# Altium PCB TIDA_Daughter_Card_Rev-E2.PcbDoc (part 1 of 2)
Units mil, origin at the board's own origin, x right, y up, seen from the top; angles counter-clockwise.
Board outline 3149.06 x 866.14 mil, 6 copper layers (L1-Top Layer, L2-GND1, L3-SIG1, L4-PWR, L5-GND2, L6-Bottom Layer), stack 0 mil thick; 80 components, 50 nets, 307 pads, 118 vias.
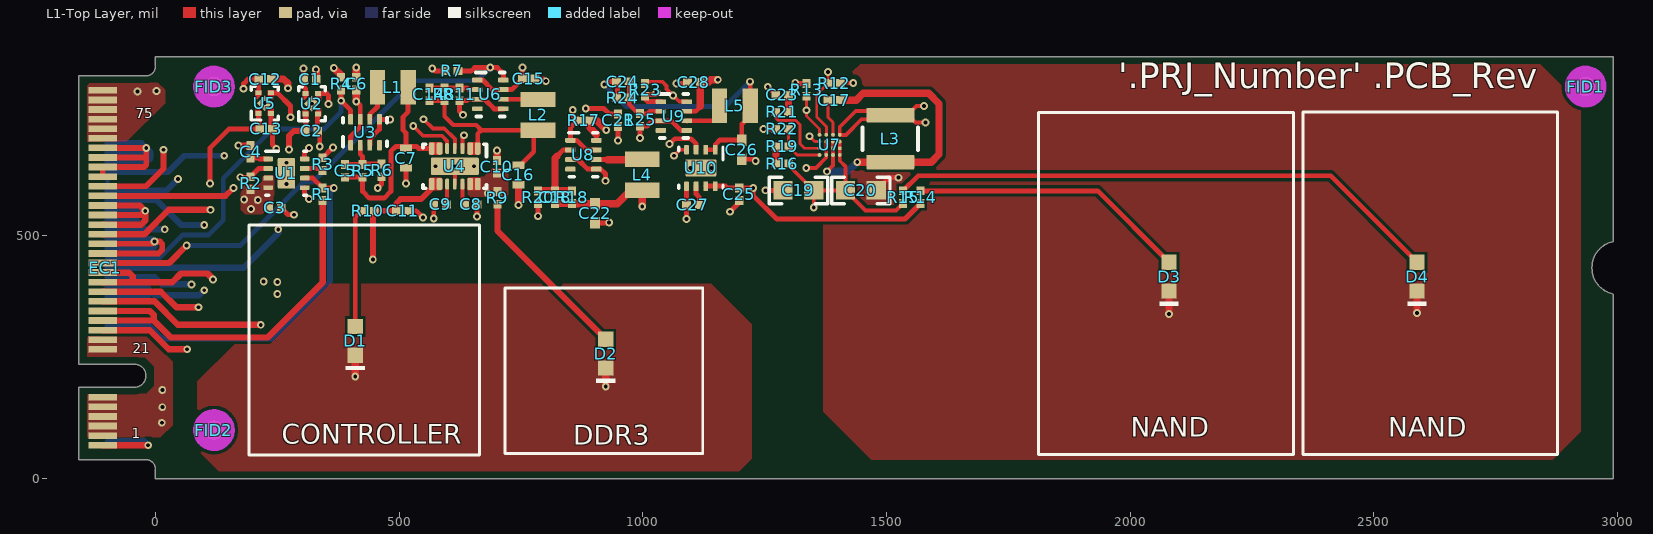
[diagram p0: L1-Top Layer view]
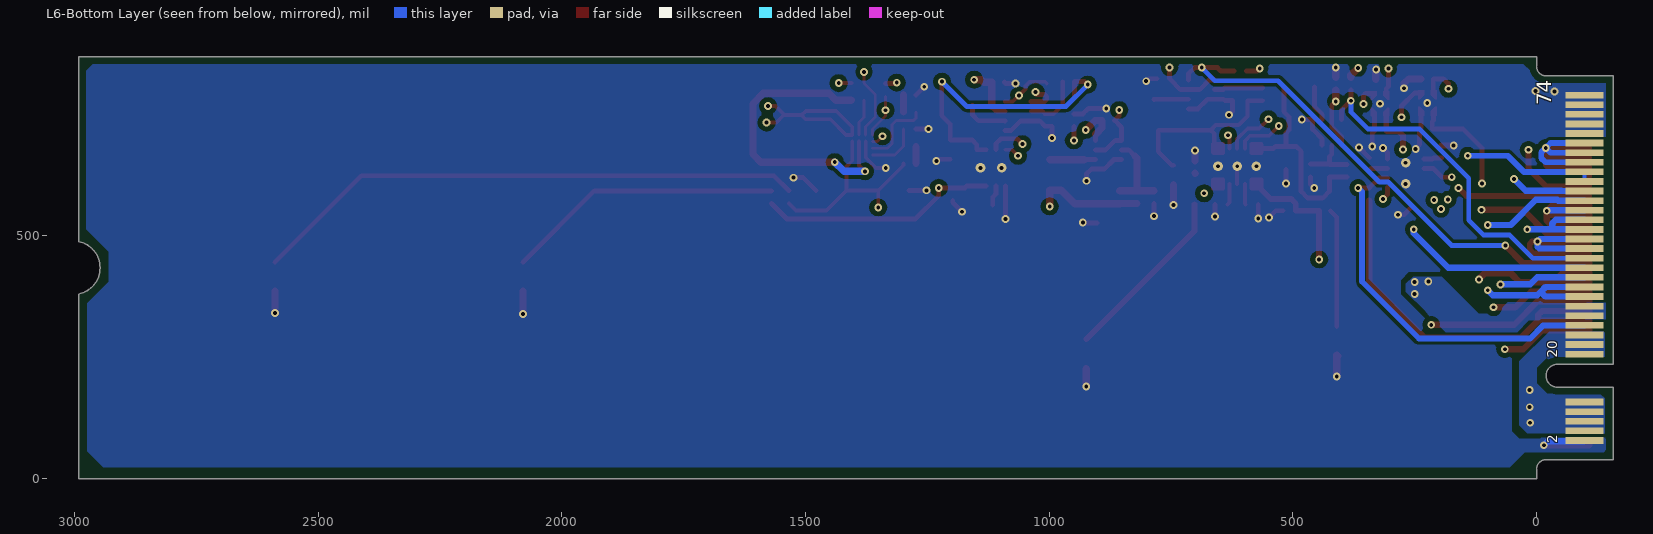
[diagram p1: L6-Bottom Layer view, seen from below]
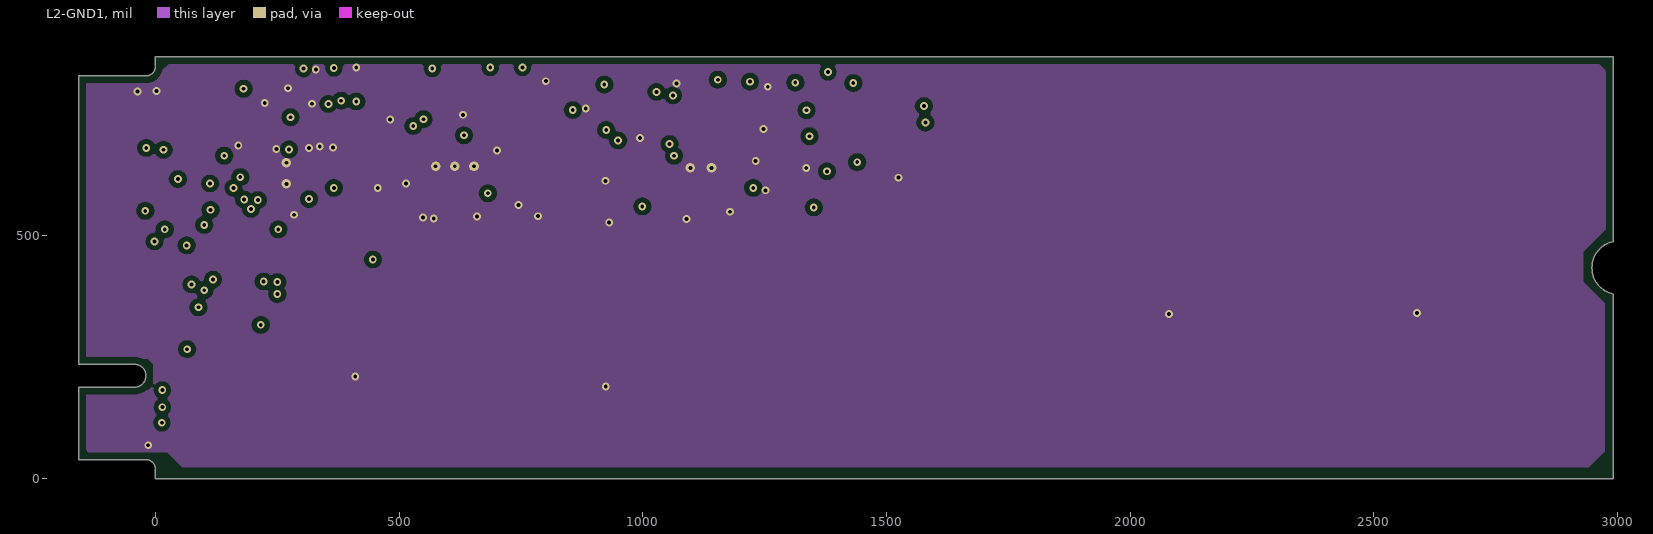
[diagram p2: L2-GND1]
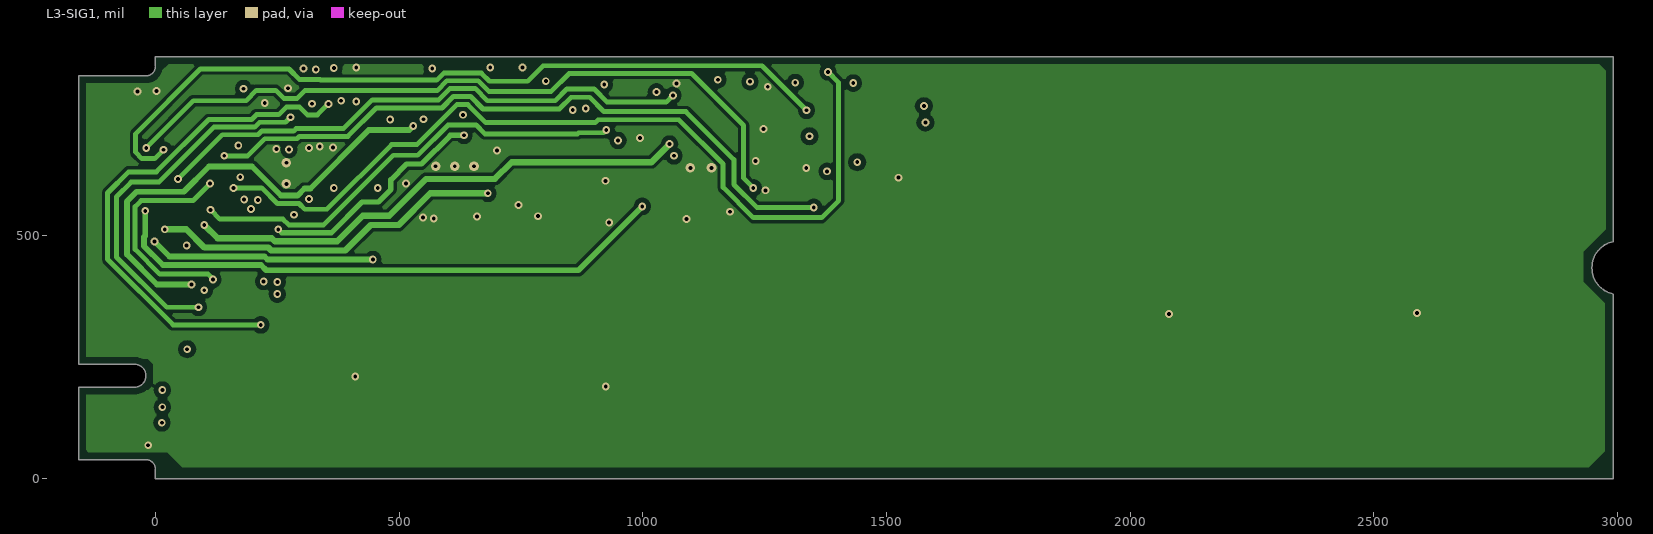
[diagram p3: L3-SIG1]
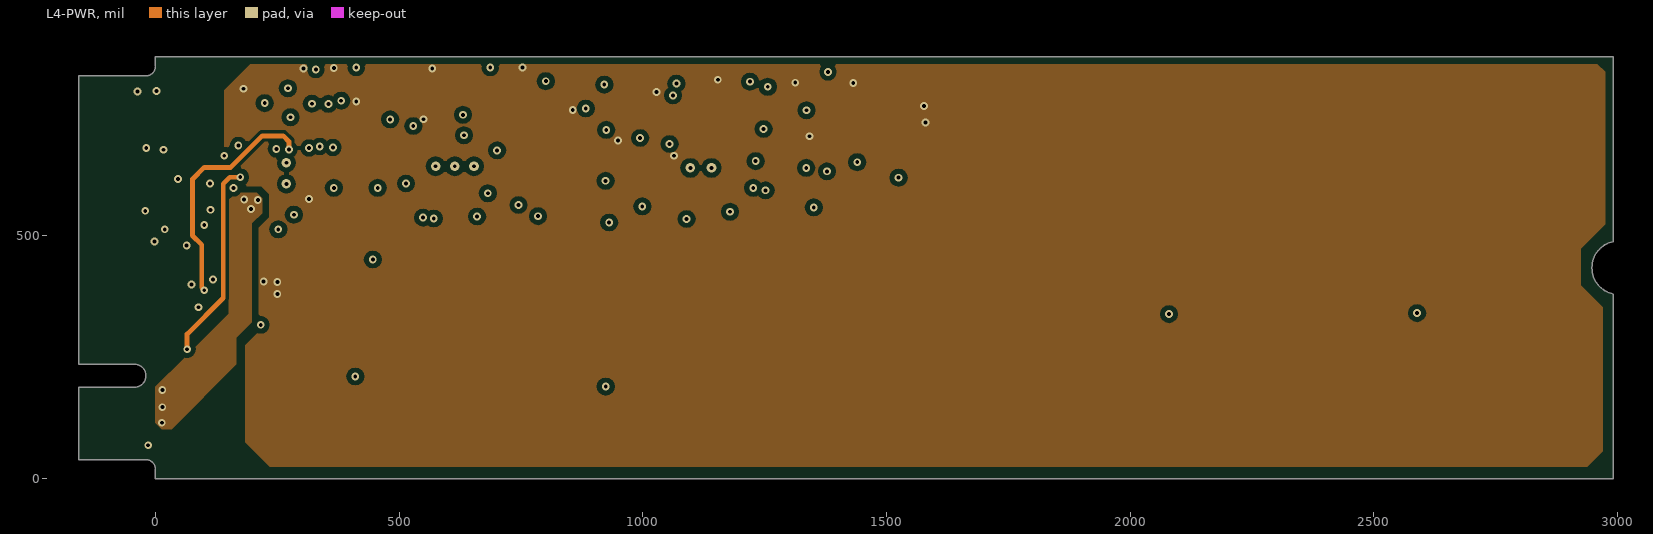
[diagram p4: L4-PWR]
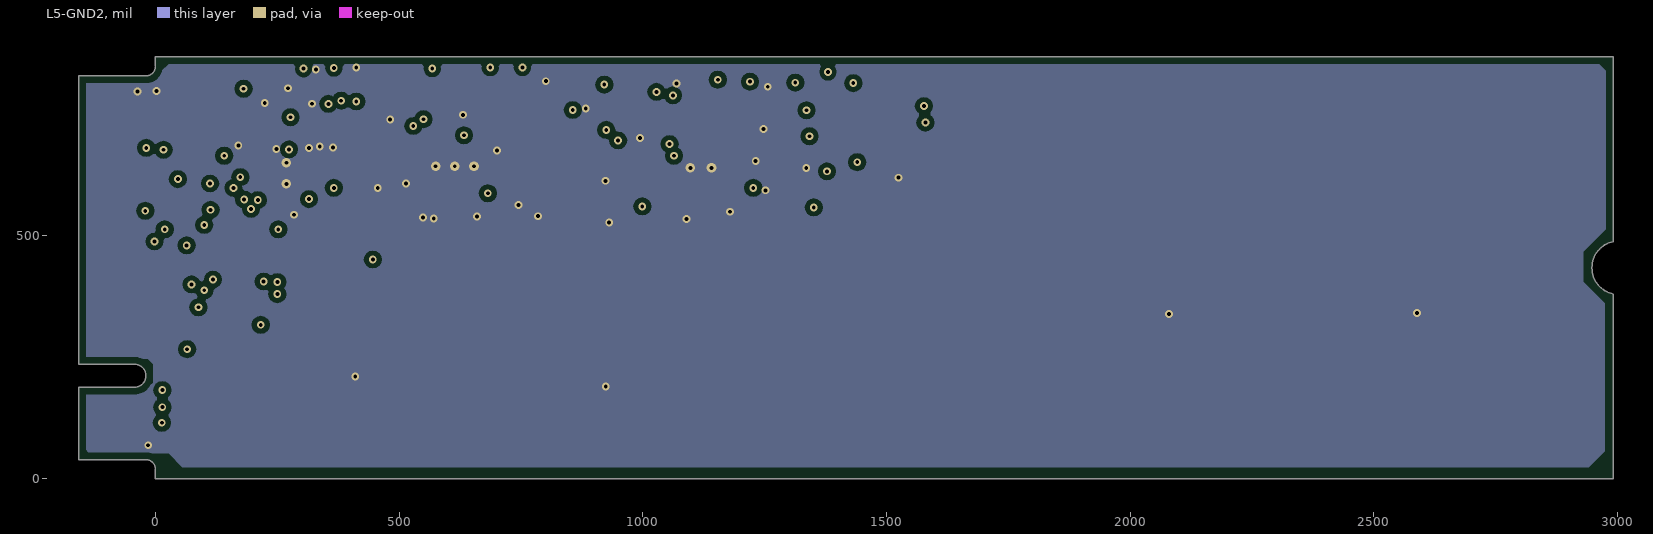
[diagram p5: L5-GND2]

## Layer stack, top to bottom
L1-Top Layer: signal copper (thickness not stored)
L2-GND1: signal copper (thickness not stored)
L3-SIG1: signal copper (thickness not stored)
L4-PWR: signal copper (thickness not stored)
L5-GND2: signal copper (thickness not stored)
L6-Bottom Layer: signal copper (thickness not stored)

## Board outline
-157.48,187.99 -43.31,187.99 ccw(c-43.31,211.61) -43.31,235.24 -157.48,235.24 -157.48,826.77 -19.69,826.77 ccw(c-19.69,846.46) 0,846.46 0,866.14 2991.58,866.14 2991.58,486.9 2991.54,486.9 ccw(c3002.82,433.07) 2991.54,379.24 2991.58,379.24 2991.58,0.39 2991.18,0 0,0 0,19.69 ccw(c-19.69,19.69) -19.69,39.37 -157.48,39.37

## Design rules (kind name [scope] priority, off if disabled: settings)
AcuteAngle [All] p1: minimum=4.50000000000000E+0001 checktracksonly=FALSE
AssemblyTestPointUsage [All] p1: valid=2
BoardOutlineClearance BoardOutlineClearance_MountingHoles [OnCopper and InComponentClass('Mounting Holes')] p1: gap=40 ignorepadtopadclearanceinfootprint=FALSE
BoardOutlineClearance BoardOutlineClearance_Poly [OnCopper and IsPoly] p2: gap=15 ignorepadtopadclearanceinfootprint=FALSE
BoardOutlineClearance [OnCopper and Not InComponentClass('Logo') and not InComponentClass('FiducialMark') and not InRegion(1000,500,4000,800) and not InPoly] p3: gap=12 ignorepadtopadclearanceinfootprint=FALSE
Clearance "U2 and U5 Pad Class" [(InPadClass('U2 AND U5'))] p1: gap=8 ignorepadtopadclearanceinfootprint=TRUE except(0: Arc-Hole Track-Hole SMDPad-Hole THPad-Hole Via-Hole Fill-Hole Poly-Hole Region-Hole Text-Hole; 4.6: Track-SMDPad SMDPad-Region; 6: Arc-Arc Arc-Track Arc-SMDPad Track-Track; 6.8: Via-Poly Via-Region; 7.4: SMDPad-Via)
Clearance Clearance_Keepouts [((IsTrack Or IsArc) And Not InPoly) And IsFree and IsKeepOut vs ((IsTrack Or IsArc) And Not InPoly) And IsFree and IsKeepOut] p2: gap=0 ignorepadtopadclearanceinfootprint=TRUE
Clearance Clearance_Poly [InPolygon] p3: gap=10 ignorepadtopadclearanceinfootprint=TRUE except(6: SMDPad-Fill SMDPad-Poly SMDPad-Region Fill-Fill Fill-Poly Fill-Region Poly-Poly Poly-Region Region-Region; 7: Arc-Fill Arc-Poly Arc-Region Track-Fill Track-Poly Track-Region)
Clearance Clearance_FiducialMark [IsKeepOut and InComponentClass('FiducialMark') vs IsPad and InComponentClass('FiducialMark')] p4: gap=0 ignorepadtopadclearanceinfootprint=FALSE
Clearance [All] p5: gap=7.87 ignorepadtopadclearanceinfootprint=TRUE except(0: Arc-Hole Track-Hole SMDPad-Hole THPad-Hole Via-Hole Fill-Hole Poly-Hole Region-Hole Text-Hole; 5.6: Arc-SMDPad Track-SMDPad; 5.7: Arc-Arc Arc-Track Track-Track; 5.8: Track-Region; 5.9: SMDPad-Poly SMDPad-Region; 6.1: Via-Region; 10: Fill-Poly Poly-Poly)
ComponentClearance ComponentClearance_MountingHoles_FiducialMarks [InComponentClass('Mounting Holes') vs InComponentClass('FiducialMark')] p1: gap=50 collisioncheckmode=3 verticalgap=10 showdistances=FALSE
ComponentClearance ComponentClearance_Shunt [InComponentClass('Header') vs InComponentClass('Shunt')] p2: gap=0 collisioncheckmode=3 verticalgap=0 showdistances=FALSE
ComponentClearance ComponentClearance_Logo [InComponentClass('Logo')] p3: gap=50 collisioncheckmode=3 verticalgap=10 showdistances=FALSE
ComponentClearance ComponentClearance_ScrewToNut [(HasFootprint('NY PMS 440 0025 PH')) vs (HasFootprint('Keystone_1902C'))] p4: gap=5 collisioncheckmode=3 verticalgap=10 showdistances=FALSE
ComponentClearance ComponentClearance_MountingHoles [InComponentClass('Mounting Holes')] p5: gap=250 collisioncheckmode=3 verticalgap=100000 showdistances=FALSE
ComponentClearance ComponentClearance_SmallPassives [HasFootprint('0201*') or HasFootprint('0402*') or HasFootprint('0508') or HasFootprint('0603*') or HasFootprint('0612') or HasFootprint('0805*') or HasFootprint('0815*') or HasFootprint('0830*') or HasFootprint('1206*') or HasFootprint('1210*') or HasFootprint('1808*') or HasFootprint('1812*') or HasFootprint('1825*') or HasFootprint('2010*') or HasFootprint('2220*') or HasFootprint('2225*') or HasFootprint('2512*') or HasFootprint('2728*') or HasFootprint('3518*') vs HasFootprint('0201*') or HasFootprint('0402*') or HasFootprint('0508') or HasFootprint('0603*') or HasFootprint('0612') or HasFootprint('0805*') or HasFootprint('0815*') or HasFootprint('0830*') or HasFootprint('1206*') or HasFootprint('1210*') or HasFootprint('1808*') or HasFootprint('1812*') or HasFootprint('1825*') or HasFootprint('2010*') or HasFootprint('2220*') or HasFootprint('2225*') or HasFootprint('2512*') or HasFootprint('2728*') or HasFootprint('3518*')] p6: gap=14.96 collisioncheckmode=3 verticalgap=10 showdistances=FALSE
ComponentClearance ComponentClearance_THtoSMT [IsThruComponent vs IsSMTComponent] p7: gap=40 collisioncheckmode=3 verticalgap=30 showdistances=FALSE
ComponentClearance ComponentClearance_THtoTH [IsThruComponent vs IsThruComponent] p8: gap=30 collisioncheckmode=3 verticalgap=30 showdistances=FALSE
ComponentClearance [All] p9: gap=15 collisioncheckmode=3 verticalgap=10 showdistances=FALSE
DiffPairsRouting [All] p1: maxlimit=100 minlimit=10 mostfreqgap=10 toplayer_minwidth=15 toplayer_maxwidth=15 toplayer_prefwidth=15 midlayer1_minwidth=15 midlayer1_maxwidth=15 midlayer1_prefwidth=15 midlayer2_minwidth=15 midlayer2_maxwidth=15 midlayer2_prefwidth=15 midlayer3_minwidth=15 midlayer3_maxwidth=15 midlayer3_prefwidth=15 midlayer4_minwidth=15 midlayer4_maxwidth=15 midlayer4_prefwidth=15 bottomlayer_minwidth=15 bottomlayer_maxwidth=15 bottomlayer_prefwidth=15 maxuncoupledlength=1000
FabricationTestPointUsage TestPointUsage [All] p1: valid=2 allowmultiple=FALSE
FabricationTestpoint Testpoint [All] p1: side=3 testpointundercomponent=TRUE minsize=40 maxsize=100 preferedsize=60 minholesize=0 maxholesize=40 preferedholesize=32 testpointgrid=1 allowsidetop=TRUE allowsidebottom=TRUE usegrid=TRUE gridtolerance=0.01
FanoutControl Fanout_LCC [IsLCC] p1: bgadir=Out bgaviamode=Centered fanoutstyle=Auto fanoutdirection=Alternating viagrid=1 // Fanout_LCC (Default Rule)
FanoutControl Fanout_BGA [IsBGA] p2: bgadir=Out bgaviamode=Centered fanoutstyle=Auto fanoutdirection=Alternating viagrid=1 // Fanout_BGA (Default Rule)
FanoutControl Fanout_Default [All] p4: bgadir=Out bgaviamode=Centered fanoutstyle=Auto fanoutdirection=Alternating viagrid=1 // Fanout_Default (Default Rule)
FanoutControl Fanout_Small [(CompPinCount < 5)] p5: bgadir=Out bgaviamode=Centered fanoutstyle=Auto fanoutdirection=OutThenIn viagrid=1 // Fanout_Small (Default Rule)
HoleSize [All] p1: absolutevalues=TRUE maxlimit=251 minlimit=7.87 maxpercent=80.000 minpercent=20.000
MinimumAnnularRing MinimumAnnularRing_ThermalPadVias [IsVia and InAnyComponent] p1: minimumring=5.91
MinimumAnnularRing [All] p2: minimumring=4
MinimumSolderMaskSliver MinimumSolderMaskSliver_Logo [InComponentClass('Logo') vs InComponentClass('Logo')] p1: minsoldermaskwidth=0.7
MinimumSolderMaskSliver [All] p2: minsoldermaskwidth=3.2
PlaneConnect [All] p1: planeconnectstyle=Direct reliefexpansion=10 reliefentries=4 reliefconductorwidth=10 reliefairgap=10
PolygonConnect [All] p1: connectstyle=Direct reliefconductorwidth=10 reliefentries=4 polygonreliefangle="90 Angle" airgapwidth=10
RoutingVias ThermalPadVias [IsVia and InAnyComponent] p1: holewidth=7.87 width=19.68 viastyle="Through Hole" minholewidth=7.87 minwidth=19.68 maxholewidth=12.99 maxwidth=23.62
RoutingVias [All] p2: holewidth=8 width=24 viastyle="Through Hole" minholewidth=7.87 minwidth=16 maxholewidth=40 maxwidth=65
SilkToBoardRegionClearance [Not ((IsComment or IsDesignator) And (Hide <> 'False')) and not InRegion(1000,500,4000,800)] p1:
SilkToSilkClearance SilkToSilkClearance_Pb-FreeLogo [(HasFootprint('Pb-Free_Overlay_Medium') OR HasFootprint('Pb-Free_Overlay_Small')) vs (HasFootprint('Pb-Free_Overlay_Medium') OR HasFootprint('Pb-Free_Overlay_Small'))] p1: silktosilkclearance=0
SilkToSilkClearance [All] p2: silktosilkclearance=2
SilkToSolderMaskClearance SilkToComponentPadClearance [(IsPad or IsFill or IsRegion) and InAnycomponent] p1: minsilkscreentomaskgap=3 clearancetoexposedcopper=TRUE
SilkToSolderMaskClearance "Silk to Solder Mask Opening" [All] p2: minsilkscreentomaskgap=3 clearancetoexposedcopper=FALSE
SolderMaskExpansion [All] p1: expansion=1.97
Width [All] p1: maxlimit=100 minlimit=6 preferedwidth=10 checkconnectedcopper=TRUE
15 further rules are at their usual default settings.

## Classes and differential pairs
component class Sheet1: U?
component class Daughter_Card_Sheet2: C1 C2 C5 C6 C7 C8 C9 C10 C11 C12 C13 C14 C15 C16 C17 C18 C19 C20 C21 C22 C23 C24 C25 C26 C27 C28 D1 D2 D3 D4 L1 L2 L3 L4 L5 R4 R5 R6 R7 R8 R9 R10 R11 R12 R13 R14 R15 R16 R17 R18 R19 R20 R21 R22 R23 R24 R25 U2 U3 U4 U5 U6 U7 U8 U9 U10
component class Daughter_Card_Sheet1: C3 C4 EC1 R1 R2 R3 U1
component class EVM_Hardware: FID1 FID2 FID3 ZZ1 ZZ2 ZZ3 ZZ4
component class FiducialMark: FID1 FID2 FID3
component class AssemblyNote: ZZ1 ZZ2 ZZ3 ZZ4
pad class "U2 AND U5": U2-1 U2-2 U2-3 U2-4 U2-5 U5-1 U5-2 U5-3 U5-4 U5-5

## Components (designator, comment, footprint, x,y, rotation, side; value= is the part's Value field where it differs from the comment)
C1 "GRM033R60J104KE19D" 0201_033 317,820 r0 top value=0.1uF
C2 "GRM033R60J104KE19D" 0201_033 319.84,713.82 r0 top value=0.1uF
C3 "GRM033R60J104KE19D" 0201_033 245,556 r0 top value=0.1uF
C4 "GRM033R60J103KA01D" 0201 195,670.99 r90 top value=0.01uF
C5 "GRM033R71C101KA01D" 0201 389,632 r90 top value=100pF
C6 "GRM035R60J475ME15D" 0201 412,811.01 r90 top value=4.7uF
C7 "GRM155R60J226ME11D" 0402S 514,658.38 r270 top value=22uF
C8 "GRM033R71C102KA01D" 0201 647,563 r0 top value=1000pF
C9 "GRM033R71C102KA01D" 0201 584.01,563 r180 top value=1000pF
C10 "CL03A105MP3NSNC" 0201 700.79,640 r90 top value=1uF
C11 "CL03A105MP3NSNC" 0201 507,550 r0 top value=1uF
C12 "GRM033R60J104KE19D" 0201_033 224.8,820.48 r0 top value=0.1uF
C13 "GRM033R60J104KE19D" 0201_033 227,718 r0 top value=0.1uF
C14 "GRM033R71C101KA01D" 0201 562,789 r90 top value=100pF
C15 "GRM035R60J475ME15D" 0201 766.01,821 r0 top value=4.7uF
C16 "GRM155R60J226ME11D" 0402S 744.79,623.62 r270 top value=22uF
C17 "GRM033R60J104KE19D" 0201_033 1393.01,777 r0 top value=0.1uF
C18 "GRM033R71C101KA01D" 0201 820,578 r90 top value=100pF
C19 "GRM188R61E106MA73D" 0603 1319.44,592 r180 top value=10uF
C20 "GRM188R61E106MA73D" 0603 1447.44,592 r0 top value=10uF
C21 "GRM035R60J475ME15D" 0201 949.36,736 r90 top value=4.7uF
C22 "GRM155R60J226ME11D" 0402L 902,545 r270 top value=22uF
C23 "GRM033R71E681KA01D" 0201 1286.01,788 r0 top value=680pF
C24 "GRM033R71C101KA01D" 0201 959,815 r0 top value=100pF
C25 "GRM033R60J104KE19D" 0201_033 1198,584 r270 top value=0.1uF
C26 "GRM155R60J226ME11D" 0402L 1203,675.62 r270 top value=22uF
C27 "GRM033R71C102KA01D" 0201 1103,562 r180 top value=1000pF
C28 "GRM035R60J475ME15D" 0201 1105,814 r180 top value=4.7uF
D1 "LB Q39G-L2N2-35-1" "LB Q39G_BLUE" 410,283 r270 top value=Blue
D2 "LB Q39G-L2N2-35-1" "LB Q39G_BLUE" 924,257 r270 top value=Blue
D3 "LB Q39G-L2N2-35-1" "LB Q39G_BLUE" 2080,415 r270 top value=Blue
D4 "LB Q39G-L2N2-35-1" "LB Q39G_BLUE" 2589,415 r270 top value=Blue
EC1 "EDGE_CONN_SM3ZS067U310ABR1200" JAE_EDGE_CONN_SM3ZS067U310ABR1200 -108.27,433.07 r90 top locked
FID1 "Fiducial" Fiducial10-20 2935,805 r0 top
FID2 "Fiducial" Fiducial10-20 120,100 r0 top
FID3 "Fiducial" Fiducial10-20 120,805 r0 top
L1 "DFE201610E-R47M=P2" DFE201610E 487,804 r180 top value=470nH
L2 "DFE201610E-R47M=P2" DFE201610E 785,747 r90 top value=470nH
L3 "DFE322512F-2R2M=P2" DFE322512 1508,698 r270 top value=2.2uH
L4 "DFE201610E-R47M=P2" DFE201610E 999,624 r90 top value=470nH
L5 "DFE201610E-R47M=P2" DFE201610E 1189,766 r180 top value=470nH
R1 "RC0201JR-07100KL" 0201 343,584 r270 top value=100k
R2 "RC0201JR-07100KL" 0201 195,606.99 r270 top value=100k
R3 "RC0201FR-07536RL" 0201 343,646 r270 top value=536
R4 "RC0201JR-07100KL" 0201 381,811 r90 top value=100k
R5 "RC0201FR-0790K9L" 0201 425,632 r270 top value=90.9k
R6 "RC0201JR-07100KL" 0201 464,633 r90 top value=100k
R7 "RC0201JR-07100KL" 0201 608,837 r180 top value=100k
R8 "RC0201FR-07150KL" 0201 593,789.01 r270 top value=150k
R9 "RC0201JR-07100RL" 0201 701.6,576.33 r90 top value=100
R10 "RC0201JR-07100RL" 0201 436,550 r0 top value=100
R11 "RC0201JR-07100KL" 0201 624,789.01 r90 top value=100k
R12 "RC0201JR-07100KL" 0201 1393.01,812 r0 top value=100k
R13 "RC0201JR-07100KL" 0201 1336,798 r270 top value=100k
R14 "RC0201JR-07100RL" 0201 1570,578.01 r270 top value=100
R15 "RC0201JR-07100RL" 0201 1534.12,578.06 r270 top value=100
R16 "RC0201JR-07910KL" 0201 1286.44,647 r0 top value=910k
R17 "RC0201JR-07100KL" 0201 878.75,735.53 r180 top value=100k
R18 "RC0201JR-07100KL" 0201 855,578 r270 top value=100k
R19 "RC0201FR-071ML" 0201 1286.44,682 r180 top value=1.00Meg
R20 "RC0201JR-07100KL" 0201 785,578 r90 top value=100k
R21 "RC0201FR-0761K9L" 0201 1286.01,753 r180 top value=61.9k
R22 "RC0201JR-07100KL" 0201 1286.01,718 r0 top value=100k
R23 "RC0201JR-07100KL" 0201 1005,798 r270 top value=100k
R24 "RC0201FR-07365KL" 0201 959,782 r180 top value=365k
R25 "RC0201JR-07100KL" 0201 994.57,736.58 r90 top value=100k
U1 "TPS259521DSGR" DSG0008A 268.6,626.99 r0 top
U2 "TLV74333PDQNR" DQN0004A 321.03,769.81 r90 top
U3 "TPS62821DLCR" DLC0008A 430,711 r90 top
U4 "TPS22976DPUR" DPU0014A 614.25,641.42 r270 top
U5 "TLV74318PDQNR" DQN0004A 224.1,771.07 r90 top
U6 "TPS62821DLCR" DLC0008A 687.21,788.84 r0 top
U7 "TPS61372YKBT" YKB0016AEAG 1383.5,685.24 r90 top
U8 "TPS62821DLCR" DLC0008A 878.17,665.06 r0 top
U9 "TPS62822DLCR" DLC0008A 1063.8,744.47 r0 top
U10 "TPS22975DSGR" DSG0008A 1119.28,638 r270 top
ZZ1 "This Assembly Note is for PCB labels only" AssemblyNoteLabel 26.57,2103.91 r0 top
ZZ2 "These assemblies are ESD sensitive, ESD precautions shall be observed." AssemblyNote 26.57,1995.02 r0 top
ZZ3 "These assemblies must be clean and free from flux and all contaminants. Use of no clean flux is not acceptable." AssemblyNote 26.57,1906.46 r0 top
ZZ4 "These assemblies must comply with workmanship standards IPC-A-610 Class 2, unless otherwise specified." AssemblyNote 26.57,1817.91 r0 top

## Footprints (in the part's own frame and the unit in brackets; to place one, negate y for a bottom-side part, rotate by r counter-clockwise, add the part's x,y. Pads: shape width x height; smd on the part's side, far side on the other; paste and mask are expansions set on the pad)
0201 [mm] "Data from Kemet datasheet CC101_COM dated 7/28/11"
  rect 0.46x0.42 smd mask+0.048: 1(-0.33,0) 2(0.33,0)
  body extent -0.31,-0.16 0.31,0.16, height 0.26
0201_033 [mm] "SMD, 2-Leads, Height 0.33mm"
  rect 0.46x0.42 smd mask+0.048: 1(-0.33,0) 2(0.33,0)
  body extent -0.31,-0.16 0.31,0.16, height 0.33
0402L [mm] "0402 from SM-752 data"
  rect 0.6x0.5 smd: 1(-0.5,0) 2(0.5,0)
  body extent -0.55,-0.3 0.55,0.3, height 0.6
0402S [mil] "Based on C0402S footprint from PADS legacy"
  rect 15x24 smd: 1(-20,0) 2(20,0)
  body extent -22,-12 22,12, height 24
0603 [mm] "0603 from SM-752 data"
  rect 1x0.95 smd: 1(-0.8,0) 2(0.8,0)
  silkscreen extent -1.52,-0.69 1.52,0.69, body extent -0.87,-0.47 0.87,0.47, height 1
AssemblyNote [mil] "Assembly Note"
AssemblyNoteLabel [mil] "Assembly Note for PCB Labels"
DFE201610E [mm] "MuRata"
  rect 0.8x1.8 smd: 1(0.8,0) 2(-0.8,0)
  body extent -1.1,-0.9 1.1,0.9, height 1
DFE322512 [mm] "MuRata"
  rrect13% 0.75x2.5 smd: 1(-1.225,0) 2(1.225,0)
  silkscreen extent -0.6,-1.45 0.6,1.45, body extent -1.7,-1.35 1.7,1.35, height 1.2
DLC0008A [mm] "VSON-HR-8"
  rrect40% 0.55x0.25 smd: 1(-0.675,0.75) 2(-0.675,0.25) 3(-0.675,-0.25) 4(-0.675,-0.75) 5(0.675,-0.75) 6(0.675,-0.25) 7(0.675,0.25) 8(0.675,0.75)
  silkscreen extent -0.75,-1.15 0.75,1.15, body extent -0.8,-1.05 0.8,1.05, height 1.02
DPU0014A [mm] "SON-14"
  rrect67% 0.65x0.3 smd paste-0.05 mask-0.05: 1(-0.925,1.2) 2(-0.925,0.8) 6(-0.925,-0.8) 7(-0.925,-1.2) 8(0.925,-1.2) 9(0.925,-0.8) 13(0.925,0.8) 14(0.925,1.2)
  rrect50% 0.55x0.2 smd: 3(-0.925,0.4) 4(-0.925,0) 5(-0.925,-0.4) 10(0.925,-0.4) 11(0.925,0) 12(0.925,0.4)
  rrect12% 0.85x1.11 on Top Paste: 15(0,0.655) 15(0,-0.655)
  rrect11% 0.9x2.5 smd paste-0.5: 15(0,0)
  L1-Top Layer region: -0.6,0.75 -0.6,1.25 -0.613,1.3 -0.65,1.337 -0.7,1.35 -0.7,1.35 -1.15,1.35 -1.188,1.342 -1.221,1.321 -1.242,1.288 -1.25,1.25 -1.25,1.25 -1.25,0.75 -1.242,0.712 -1.221,0.679 -1.188,0.658 -1.15,0.65 -1.15,0.65 -0.7,0.65 -0.662,0.658 -0.629,0.679 -0.608,0.712 -0.6,0.75
  L1-Top Layer region: -0.6,-0.75 -0.6,-1.25 -0.613,-1.3 -0.65,-1.337 -0.7,-1.35 -0.7,-1.35 -1.15,-1.35 -1.188,-1.342 -1.221,-1.321 -1.242,-1.288 -1.25,-1.25 -1.25,-1.25 -1.25,-0.75 -1.242,-0.712 -1.221,-0.679 -1.188,-0.658 -1.15,-0.65 -1.15,-0.65 -0.7,-0.65 -0.662,-0.658 -0.629,-0.679 -0.608,-0.712 -0.6,-0.75
  L1-Top Layer region: 0.6,-0.75 0.6,-1.25 0.613,-1.3 0.65,-1.337 0.7,-1.35 0.7,-1.35 1.15,-1.35 1.188,-1.342 1.221,-1.321 1.242,-1.288 1.25,-1.25 1.25,-1.25 1.25,-0.75 1.242,-0.712 1.221,-0.679 1.188,-0.658 1.15,-0.65 1.15,-0.65 0.7,-0.65 0.662,-0.658 0.629,-0.679 0.608,-0.712 0.6,-0.75
  L1-Top Layer region: 0.6,0.75 0.6,1.25 0.613,1.3 0.65,1.337 0.7,1.35 0.7,1.35 1.15,1.35 1.188,1.342 1.221,1.321 1.242,1.288 1.25,1.25 1.25,1.25 1.25,0.75 1.242,0.712 1.221,0.679 1.188,0.658 1.15,0.65 1.15,0.65 0.7,0.65 0.662,0.658 0.629,0.679 0.608,0.712 0.6,0.75
  silkscreen extent -1.15,-1.65 1.15,1.65, body extent -1.05,-1.55 1.05,1.55, height 0.8
DQN0004A [mm] "SON, 0.65mm pitch"
  rect 0.25x0.31 smd paste-1 mask-0.31: 1(-0.535,0.325) 2(-0.535,-0.325) 3(0.535,-0.325) 4(0.535,0.325)
  rect 0.58x0.58 smd rot 45 paste-0.065: 5(0,0)
  L1-Top Layer region: -0.66,0.48 -0.2,0.48 -0.2,0.379 -0.409,0.17 -0.66,0.17
  L1-Top Layer region: 0.66,0.48 0.2,0.48 0.2,0.379 0.409,0.17 0.66,0.17
  L1-Top Layer region: 0.66,-0.48 0.2,-0.48 0.2,-0.379 0.409,-0.17 0.66,-0.17
  L1-Top Layer region: -0.66,-0.48 -0.2,-0.48 -0.2,-0.379 -0.409,-0.17 -0.66,-0.17
  silkscreen extent -0.88,-0.7 0.88,0.7, body extent -0.53,-0.53 0.53,0.53, height 0.42
DSG0008A [mm] "SON, 8-Leads, Body 2x2mm, Pitch 0.5mm, Thermal Pad 1.6x0.9mm, TI Recommended"
  rrect40% 0.5x0.25 smd: 1(-0.95,0.75) 2(-0.95,0.25) 3(-0.95,-0.25) 4(-0.95,-0.75) 5(0.95,-0.75) 6(0.95,-0.25) 7(0.95,0.25) 8(0.95,0.75)
  rrect14% 0.9x0.7 on Top Paste: 9(0,-0.45) 9(0,0.45)
  rrect11% 0.9x1.6 smd paste-0.45: 9(0,0)
  silkscreen extent -1.07,-1.15 1.07,1.15, body extent -1,-1 1,1, height 0.77
Fiducial10-20 [mm]
  round 1 smd mask+0.5: 1(0,0)
  L1-Top Layer keep-out circle w1.178: c0,0 r0.5
JAE_EDGE_CONN_SM3ZS067U310ABR1200 [mm] "Edge footprint connector 67 pins"
  rect 0.35x1.5 smd paste-0.2: 1(-9.25,0) 3(-8.75,0) 5(-8.25,0) 7(-7.75,0) 9(-7.25,0) 11(-6.75,0) 21(-4.25,0) 23(-3.75,0) 25(-3.25,0) 27(-2.75,0) 29(-2.25,0) 31(-1.75,0) 33(-1.25,0) 35(-0.75,0) 37(-0.25,0) 39(0.25,0) 41(0.75,0) 43(1.25,0) 45(1.75,0) 47(2.25,0) 49(2.75,0) 51(3.25,0) 53(3.75,0) 55(4.25,0) 57(4.75,0) 59(5.25,0) 61(5.75,0) 63(6.25,0) 65(6.75,0) 67(7.25,0) 69(7.75,0) 71(8.25,0) 73(8.75,0) 75(9.25,0)
  rect 0.35x2 smd far side paste-0.2: 2(-9,-0.25) 4(-8.5,-0.25) 6(-8,-0.25) 8(-7.5,-0.25) 10(-7,-0.25) 20(-4.5,-0.25) 22(-4,-0.25) 24(-3.5,-0.25) 26(-3,-0.25) 28(-2.5,-0.25) 30(-2,-0.25) 32(-1.5,-0.25) 34(-1,-0.25) 36(-0.5,-0.25) 38(0,-0.25) 40(0.5,-0.25) 42(1,-0.25) 44(1.5,-0.25) 46(2,-0.25) 48(2.5,-0.25) 50(3,-0.25) 52(3.5,-0.25) 54(4,-0.25) 56(4.5,-0.25) 58(5,-0.25) 60(5.5,-0.25) 62(6,-0.25) 64(6.5,-0.25) 66(7,-0.25) 68(7.5,-0.25) 70(8,-0.25) 72(8.5,-0.25) 74(9,-0.25)
"LB Q39G_BLUE" [mm] "OSRAM"
  rect 0.8x0.8 smd: 1(-0.75,0) 2(0.75,0)
  silkscreen extent 1.3,-0.5 1.52,0.5, body extent -0.85,-0.45 0.85,0.45, height 0.4
YKB0016AEAG [mm] "DSBGA-16"
  round 0.2 on Top Solder: A1(-0.525,0.525) A2(-0.175,0.525) A3(0.175,0.525) A4(0.525,0.525) B1(-0.525,0.175) B2(-0.175,0.175) B3(0.175,0.175) B4(0.525,0.175) C1(-0.525,-0.175) C2(-0.175,-0.175) C3(0.175,-0.175) C4(0.525,-0.175) D1(-0.525,-0.525) D2(-0.175,-0.525) D3(0.175,-0.525) D4(0.525,-0.525)
  round 0.2 smd paste-0.12 mask+0.032: A1(-0.525,0.525) A2(-0.175,0.525) A3(0.175,0.525) A4(0.525,0.525) B1(-0.525,0.175) B2(-0.175,0.175) B3(0.175,0.175) B4(0.525,0.175) C1(-0.525,-0.175) C2(-0.175,-0.175) C3(0.175,-0.175) C4(0.525,-0.175) D1(-0.525,-0.525) D2(-0.175,-0.525) D3(0.175,-0.525) D4(0.525,-0.525)
  body extent -0.74,-0.77 0.74,0.77, height 0.51

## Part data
C1 C2 C3 C12 C13 C17 C25: library part CMP-0009690-3, "CAP, CERM, 0.1 uF, 6.3 V, +/- 10%, X5R, 0201", Cap_Case=0201, Manufacturer=MuRata, Supplier Part Number 1=490-3167-1-ND, TempCo=X5R, Tolerance_%=10%, Value1=Unknown, Value2=6.3V, ValueDisplayed=0.1uF
C4: library part CMP-0009689-3, "CAP, CERM, 0.01 uF, 6.3 V, +/- 10%, X5R, 0201", Cap_Case=0201, Manufacturer=MuRata, Supplier Part Number 1=490-5403-1-ND, TempCo=X5R, Tolerance_%=10%, Value1=Unknown, Value2=6.3V, ValueDisplayed=0.01uF
C5 C14 C18 C24: library part CMP-0009744-1, "CAP, CERM, 100 pF, 16 V, +/- 10%, X7R, 0201", Cap_Case=0201, Manufacturer=MuRata, Supplier Part Number 1=GRM033R71C101KA01D-ND, TempCo=X7R, Tolerance_%=10%, Value1=Unknown, Value2=16V, ValueDisplayed=100pF
C6 C15 C21 C28: library part CMP-0009780-1, "CAP, CERM, 4.7 uF, 6.3 V, +/- 20%, X5R, 0201", Cap_Case=0201, Manufacturer=MuRata, Supplier Part Number 1=490-13230-1-ND, TempCo=X5R, Tolerance_%=20%, Value1=Unknown, Value2=6.3V, ValueDisplayed=4.7uF
C7 C16 C22 C26: library part CMP-0006545-2, "CAP, CERM, 22 uF, 6.3 V, +/- 20%, X5R, 0402", Cap_Case=0402, Manufacturer=MuRata, TempCo=X5R, Tolerance_%=20%, Value1=Unknown, Value2=6.3V, ValueDisplayed=22uF
C8 C9 C27: library part CMP-0009745-1, "CAP, CERM, 1000 pF, 16 V, +/- 10%, X7R, 0201", Cap_Case=0201, Manufacturer=MuRata, Supplier Part Number 1=GRM033R71C102KA01D-ND, TempCo=X7R, Tolerance_%=10%, Value1=Unknown, Value2=16V, ValueDisplayed=1000pF
C10 C11: library part CMP-0009656-3, "CAP, CERM, 1 uF, 10 V, +/- 20%, X5R, 0201", Cap_Case=0201, Manufacturer="Samsung Electro-Mechanics", TempCo=X5R, Tolerance_%=20%, Value1=Unknown, Value2=10V, ValueDisplayed=1uF
C19 C20: library part CMP-0007344-5, "CAP, CERM, 10 uF, 25 V, +/- 20%, X5R, 0603", Cap_Case=0603, Manufacturer=MuRata, Supplier Part Number 1=490-7202-1-ND, TempCo=X5R, Tolerance_%=20%, Value1=Unknown, Value2=25V, ValueDisplayed=10uF
C23: library part CMP-0009776-1, "CAP, CERM, 680 pF, 25 V, +/- 10%, X7R, 0201", Cap_Case=0201, Manufacturer=MuRata, Supplier Part Number 1=490-3182-1-ND, TempCo=X7R, Tolerance_%=10%, Value1=Unknown, Value2=25V, ValueDisplayed=680pF
D1 D2 D3 D4: library part CMP-0002849-2, "LED, Blue, SMD", Color=blue, Manufacturer=OSRAM, Value1=W, Value2=2.85V
EC1: library part CMP-0075074-1, "Connector, Card Edge 67-Pos, 0.5-mm Pitch, B Key", Manufacturer="JAE Electronics"
FID1 FID2 FID3: library part CMP-0077181-1, "Fiducial mark.  There is nothing to buy or mount.", Manufacturer=N/A
L1 L2 L4 L5: library part CMP-0077678-3, "Inductor, Shielded, Metal Composite, 470 nH, 3.6 A, 0.032 ohm, SMD", Manufacturer=MuRata, PartNumber=DFE201610E-R47M{}P2, Supplier Part Number 1=DFE201610E-R47M{}P2-ND, Value1="0.032 ohm", Value2=3.6A, ValueDisplayed=470nH
L3: library part CMP-0058590-1, "Inductor, Shielded, Metal Composite, 2.2 uH, 2.6 A, 0.066 ohm, SMD", Manufacturer=MuRata, PartNumber=DFE322512F-2R2M{}P2, Value1="0.066 ohm", Value2=2.6A, ValueDisplayed=2.2uH
R1 R2 R4 R6 R7 R11 R12 R13 R17 R18 R20 R22 R23 R25: library part CMP-0027017-1, "RES, 100 k, 5%, 0.05 W, 0201", Manufacturer="Yageo America", Power_W=50mW, Supplier Part Number 1=311-100KNCT-ND, TempCo="200 ppm/C", Tolerance_%=5%, Value2=0.05W, Value_Code=100k
R3: library part CMP-0027765-1, "RES, 536, 1%, 0.05 W, 0201", Manufacturer="Yageo America", Power_W=50mW, Supplier Part Number 1=YAG2721CT-ND, TempCo="200 ppm/C", Tolerance_%=1%, Value2=0.05W, Value_Code=536R, ValueDisplayed=536
R5: library part CMP-0027918-1, "RES, 90.9 k, 1%, 0.05 W, 0201", Manufacturer="Yageo America", Power_W=50mW, Supplier Part Number 1=YAG2838CT-ND, TempCo="200 ppm/C", Tolerance_%=1%, Value2=0.05W, Value_Code=90k9, ValueDisplayed=90.9k
R8: library part CMP-0027366-2, "RES, 150 k, 1%, 0.05 W, 0201", Manufacturer="Yageo America", Power_W=50mW, Supplier Part Number 1=YAG2272CT-ND, TempCo="200 ppm/C", Tolerance_%=1%, Value2=0.05W, Value_Code=150k
R9 R10 R14 R15: library part CMP-0027018-3, "RES, 100, 5%, 0.05 W, 0201", Manufacturer="Yageo America", Power_W=50mW, Supplier Part Number 1=311-100NCT-ND, TempCo="200 ppm/C", Tolerance_%=5%, Value2=0.05W, Value_Code=100R, ValueDisplayed=100
R16: library part CMP-0027177-1, "RES, 910 k, 5%, 0.05 W, 0201", Manufacturer="Yageo America", Power_W=50mW, Supplier Part Number 1=YAG2938CT-ND, TempCo="200 ppm/C", Tolerance_%=5%, Value2=0.05W, Value_Code=910k
R19: library part CMP-0027463-1, "RES, 1.00 M, 1%, 0.05 W, 0201", Manufacturer="Yageo America", Power_W=50mW, Supplier Part Number 1=311-1MMCT-ND, TempCo="200 ppm/C", Tolerance_%=1%, Value2=0.05W, Value_Code=1M00, ValueDisplayed=1.00M
R21: library part CMP-0027811-1, "RES, 61.9 k, 1%, 0.05 W, 0201", Manufacturer="Yageo America", Power_W=50mW, Supplier Part Number 1=YAG2751CT-ND, TempCo="200 ppm/C", Tolerance_%=1%, Value2=0.05W, Value_Code=61k9, ValueDisplayed=61.9k
R24: library part CMP-0027630-1, "RES, 365 k, 1%, 0.05 W, 0201", Manufacturer="Yageo America", Power_W=50mW, Supplier Part Number 1=YAG2623CT-ND, TempCo="200 ppm/C", Tolerance_%=1%, Value2=0.05W, Value_Code=365k
U1: library part CMP-0013452-3, "12V eFuse with Over Voltage Protection, DSG0008A (WSON-8)", Alternate Manufacturer="Texas Instruments", Alternate PartNumber=TPS259521DSGT
U2: library part CMP-0065170-2, "Low-Dropout Regulator, DQN0004A (X2SON-4)", Alternate Manufacturer="Texas Instruments"
U3 U6 U8: library part CMP-0065148-3, "1A Step-Down Converter With 1% Accuracy, DLC0008A (VSON-HR-8)", Alternate Manufacturer="Texas Instruments"
U4: library part CMP-0073686-3, "5.5V, 6A, 14mO, Dual Load Switch with Adj. Rise Time & Optional QOD, DPU0014A (WSON-14)", Alternate Manufacturer="Texas Instruments", Alternate PartNumber=TPS22976DPUT
U5: library part CMP-0065161-2, "Low-Dropout Regulator, DQN0004A (X2SON-4)", Alternate Manufacturer="Texas Instruments"
U7: library part CMP-0081181-1, "16-V, 3.6-A Synchronous Boost with Short Protection and Load Disconnect, YKB0016AEAG (DSBGA-16)", Alternate Manufacturer="Texas Instruments", Alternate PartNumber=TPS61372YKBR
U9: library part CMP-0077166-2, "2A Step-Down Converter With 1% Accuracy, DLC0008A (VSON-HR-8)", Alternate Manufacturer="Texas Instruments", Alternate PartNumber=TPS62822DLCT
U10: library part CMP-0073684-2, "5.7V, 6A, 16mO Load Switch with Adjustable Rise Time & Optional QOD for Cost-Conscious Applications, DSG0008A (WSON-8)", Alternate Manufacturer="Texas Instruments", Alternate PartNumber=TPS22975DSGT
ZZ1: library part CMP-0003616-3
ZZ2: library part CMP-0077236-1
ZZ3: library part CMP-0077237-1
ZZ4: library part CMP-0077238-1

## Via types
v1: diameter 16, hole 8, L1-Top Layer to L6-Bottom Layer, tented both sides, 111 vias
v2: diameter 19.68, hole 7.87, L1-Top Layer to L6-Bottom Layer, 7 vias

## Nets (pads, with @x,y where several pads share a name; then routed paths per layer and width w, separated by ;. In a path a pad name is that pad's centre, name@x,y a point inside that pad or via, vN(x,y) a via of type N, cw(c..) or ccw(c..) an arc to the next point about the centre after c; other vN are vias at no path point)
EN_VCC_3DNAND: EC1.52 U10.3 | length 1347.5
  L1-Top Layer w10: v1(1055,687) 1066,698 1099,698 1109.44,687.56 U10.3@1109.44,675.4
  L3-SIG1 w13: v1(100,521) 127.37,493.63 238.73,493.63 245.13,487.23 372.78,487.23 425.25,539.7 479.7,539.7 555.44,615.44 696.44,615.44 731,650 1018,650 v1(1055,687)
  L6-Bottom Layer w13: EC1.52@-98.43,570.87 -44.43,570.87 -42.92,572.37 1.63,572.37 53,521 v1(100,521)
EN_VCC_DDR3: EC1.38 U4.3 | length 894.6
  L1-Top Layer w8: U4.3@630,677.83 630,702 v1(633,705)
  L3-SIG1 w11: v1(252,512) 259.07,504.93 360.93,504.93 424,568 457.23,568 483,593.77 483,613.6 515.4,646 546,646 605,705 v1(633,705)
  L6-Bottom Layer w13: EC1.38@-98.43,433.07 181.07,433.07 252,504 v1(252,512)
EN_VCC_IO_SOC: EC1.33 U5.3 | length 1043
  L1-Top Layer w10: U5.3@236.9,792.13 249.92,792.13 277,765.06 v1(277,742)
  L1-Top Layer w13: EC1.33@-108.27,383.86 11.14,383.86 43,352 v1(88,352)
  L3-SIG1 w10: v1(88,352) 23,352 -80.09,455.09 -80.09,578.83 -49.92,609 7,609 119.7,721.7 203.77,721.7 213.78,731.71 266.71,731.71 v1(277,742)
EN_VCC_SOC: EC1.31 U2.3 | length 1432.9
  L1-Top Layer w10: U2.3@333.83,790.87 351.13,790.87 354.84,787.16 v1(354.84,769.46)
  L1-Top Layer w13: EC1.31@-108.27,364.17 -2.17,364.17 46,316 v1(216,316)
  L3-SIG1 w10: v1(216,316) 36.05,316 -98.43,450.47 -98.43,586.57 -55.08,629.92 1.92,629.92 109.4,737.4 197.27,737.4 207.28,747.41 252.89,747.41 268.35,762.87 295.62,762.87 311.56,746.94 332.32,746.94 v1(354.84,769.46)
EN_VCORE_SOC: EC1.36 U4.5 | length 1243.8
  L1-Top Layer w8: v1(529,724) 549,704 587.96,704 598.5,693.46 U4.5@598.5,677.83
  L3-SIG1 w12: v1(74,399) 3,399 -58.57,460.57 -58.57,569.43 -39,589 58,589 109.87,640.87 198.13,640.87 257.38,581.62 291.69,581.62 305.94,595.87 317.87,595.87 437.7,715.7 520.7,715.7 v1(529,724)
  L6-Bottom Layer w13: EC1.36@-98.43,413.39 -1.39,413.39 13,399 v1(74,399)
EN_VPP_3DNAND: EC1.53 R12.1 U7.B4@1376.61,705.91 | length 2187.5
  L1-Top Layer w6: U7.B4@1376.61,705.91 1376.61,723.03 1357,742.63 1357,788.98 R12.1@1380.02,812 v1(1380.02,834.98)
  L1-Top Layer w12: EC1.53@-108.27,580.71 143.71,580.71 v1(160,597)
  L3-SIG1 w10: v1(160,597) 217.88,597 249.96,564.92 294.56,564.92 306.35,553.13 351.66,553.13 484.47,685.94 536.42,685.94 618.35,767.87 641.06,767.87 677.93,731 902.35,731 908.23,736.87 1074.19,736.87 1165,646.06 1165,598 1226.94,536.06 1367.06,536.06 1402,571 1402,813 v1(1380.02,834.98)
GND: C1.2 C2.2 C3.2 C4.2 C6.2 C7.2 C8.2 C9.2 C10.2 C11.2 C12.2 C13.2 C15.2 C16.2 C19.2 C20.2 C21.2 C22.2 C23.1 C25.2 C26.2 C27.2 C28.2 D1.2 D2.2 D3.2 D4.2 EC1.1 EC1.2 EC1.65 EC1.66 EC1.67 EC1.68 EC1.69 EC1.70 EC1.71 EC1.72 EC1.73 EC1.74 EC1.75 R3.1 R6.1 R11.1 R20.1 R22.1 R25.1 U1.8 U1.9@268.6,626.99 U2.2 U2.5 U3.3 U3.5 U4.11 U4.15@614.25,641.42 U5.2 U5.5 U6.3 U6.5 U7.B1@1376.61,664.58 U7.B2@1376.61,678.36 U7.B3@1376.61,692.13 U8.3 U8.5 U9.3 U9.5 U10.5 U10.9@1119.28,638 | length 1927.1
  L1-Top Layer w8: U4.15@613.79,641.42 613.79,643 614.25,642.54 v2(614.25,641.42) U4.11@614.25,605 ; v1@1334.44,641 1335.44,640 v1(1335.44,638) 1355.47,638 1376.61,659.13 U7.B1@1376.61,664.58 U7.B2@1376.61,678.36 U7.B3@1376.61,692.13
  L1-Top Layer w10: U5.2@236.9,750.01 236.9,721.09 C13.2@239.99,718 239.99,686.01 248,678 v1(248,677) ; C3.2@257.99,556 271.99,542 v1(284,542) ; U1.8@306,656.52 306,670 v1(315,679) ; U2.2@333.83,748.75 332.84,747.76 C2.2@332.84,713.82 337,709.65 v1(337,682) ; R3.1@343,658.99 v1(364.01,680) ; U3.3@439.84,684.43 439.84,697.32 459.53,717 U3.5@459.53,737.57 v1(481.57,737.57) ; v1(456,597) 464,605 R6.1@464,620.01 ; v1(514,606.05) C7.2@514,634.76 ; C11.2@519.99,550 535,550 v1(549,536) ; v1(571.02,534.3) C9.2@571.02,563 ; v1(631,747) 624,754 R11.1@624,776.02 639.02,776.02 642,779 U6.3@660.64,779 675.16,779 694.84,759.31 U6.5@713.79,759.31 ; v1(659.99,538.3) C8.2@659.99,563 ; C15.2@779,821 796,821 v1(801,816) ; v1(785,539) R20.1@785,565.01 ; U8.3@851.6,655.21 867.06,655.21 886.75,635.53 U8.5@904.75,635.53 913.75,635.53 923.75,625.53 v1(923.75,611.53) ; v1(883,760) 920,760 931.01,748.99 C21.2@949.36,748.99 ; C22.2@902,525.31 930.31,525.31 v1(931,526) ; v1(994.57,699.43) R25.1@994.57,723.59 1008.59,723.59 1019.63,734.63 U9.3@1037.22,734.63 1058.37,734.63 1078.06,714.94 U9.5@1090.37,714.94 ; v1(1069,811) 1089.01,811 C28.2@1092.01,814 ; U10.5@1089.76,600.6 1089.76,562.25 C27.2@1090.01,562 v1(1090.01,533.3) ; v1(1179,548) 1198,567 C25.2@1198,571.01 ; C26.2@1203,655.94 1227.77,655.94 v1(1231.7,652) ; v1(1248,718) R22.1@1273.02,718 ; v1(1252,592) C19.2@1287.95,592 ; v1@1256.48,807.46 v1(1256.48,804.54) C23.1@1273.02,788 ; C20.2@1478.94,592 1504.94,618 v1(1525,618)
  L1-Top Layer w12: v1(169.98,683.98) C4.2@195,683.98
  L1-Top Layer w13: EC1.1@-108.27,68.9 v1(-15,68.9)
  L1-Top Layer w15: C12.2@237.79,820.48 262.8,820.48 271.8,811.48 v1(271.8,801.48) ; v1(329,840) 329.99,839.01 C1.2@329.99,820 ; D1.2@408,251.47 D1.2@410,253.47 v1(410,210) ; C6.2@412,824 v1(412,844) ; C10.2@700.79,652.99 701,653.2 v1(701,674) ; C16.2@744.79,603.62 745,603.41 v1(745,562) ; v1(924,189.3) D2.2@924,226.5 ; v1(2080,338) D3.2@2080,385.47 ; v1(2589,340) D4.2@2589,385.47
  L6-Bottom Layer w13: EC1.2@-96.69,77 -23.1,77 v1(-15,68.9)
  other v1: 321.03,769.81 224.1,771.07 -37,795 2,796
  other v2: 268.6,605.34 1097.63,638 1140.94,638 574.88,641.42 653.62,641.42 268.6,648.65
MODE_VPP_3DNAND: EC1.55 R13.2 U7.A4@1362.83,705.91 | length 1882.1
  L1-Top Layer w6: R13.2@1336,785.01 v1(1336,756.3) 1336,744.83 1362.83,718 U7.A4@1362.83,705.91
  L1-Top Layer w12: EC1.55@-108.27,600.39 -19.61,600.39 16.54,636.54 v1(16.54,675.25)
  L3-SIG1 w10: v1(16.54,675.25) -1.45,657.26 -28.06,657.26 -40.87,670.07 -40.87,708.13 92,841 273.92,841 295.79,819.13 337.65,819.13 338.65,818.13 576.97,818.13 591.51,832.67 668.81,832.67 685.48,816 764,816 795.57,847.57 1244.73,847.57 v1(1336,756.3)
NetC4_1: C4.1 U1.1 | length 36.8
  L1-Top Layer w10: C4.1@195,658 212,658 213.48,656.52 U1.1@231.2,656.52
NetC5_1: C5.1 C7.1 L1.2 R5.2 U4.6 U4.7 | length 435.1
  L1-Top Layer w10: C5.1@389,619.01 R5.2@425,619.01 425,590 438.87,576.13 469.13,576.13 483,590 483,672 493,682 C7.1@514,682 ; L1.2@518.5,804 518.5,753.5 508.13,743.13 508.13,715.35 514,709.48 C7.1@514,682 ; U4.7@567.01,677.83 540.04,677.83 535.88,682 C7.1@514,682
NetC5_2: C5.2 R5.1 R6.2 U3.2 | length 116.9
  L1-Top Layer w10: C5.2@389,644.99 R5.1@425,644.99 ; U3.2@420.16,684.43 420.16,666 425,661.16 R5.1@425,644.99 ; R6.2@464,645.99 426,645.99 R5.1@425,644.99
NetC8_1: C8.1 U4.12 | length 43.7
  L1-Top Layer w8: U4.12@630,605 630,567.01 C8.1@634.01,563
NetC9_1: C9.1 U4.10 | length 42.6
  L1-Top Layer w8: C9.1@597,563 598.5,564.5 U4.10@598.5,605
NetC14_1: C14.1 C16.1 L2.2 R8.2 U4.1 U4.2 | length 384.1
  L1-Top Layer w9: C14.1@562,776.01 R8.2@593,776.02 ; R8.2@593,776.02 593,744 611,726 658,726 668.5,715.5 ; U4.1@661.03,679.42 661.03,708.04 668.5,715.5 ; C16.1@744.79,643.62 748.62,643.62 776,671 776,715.5 668.5,715.5
NetC14_2: C14.2 R8.1 R11.2 U6.2 | length 100
  L1-Top Layer w10: C14.2@562,801.99 R8.1@593,802 R11.2@624,802 639.69,802 643,798.69 U6.2@660.64,798.69
NetC17_1: C17.1 U7.C4@1390.39,705.91 | length 75.4
  L1-Top Layer w6: C17.1@1380.02,777 1380.02,741.98 1390.39,731.61 U7.C4@1390.39,705.91
NetC17_2: C17.2 L3.2 U7.C1@1390.39,664.58 U7.C2@1390.39,678.36 U7.C3@1390.39,692.13 | length 631.3
  L1-Top Layer w8: v1(1378,631) 1390.39,643.39 U7.C1@1390.39,664.58 U7.C2@1390.39,678.36 U7.C3@1390.39,692.13
  L1-Top Layer w15: C17.2@1406,777 1438,777 1452,791 1587,791 1608,770 1608,666 1591.77,649.77 L3.2@1508,649.77 v1(1440.07,649.77)
  L6-Bottom Layer w15: v1(1378,631) 1421.3,631 v1(1440.07,649.77)
NetC18_2: C18.2 R18.1 R20.2 U8.2 | length 175.6
  L1-Top Layer w10: 824,662 836.9,674.9 U8.2@851.6,674.9
  L1-Top Layer w15: R20.2@785,590.99 C18.2@820,590.99 ; 824,662 820,658 C18.2@820,590.99 ; R18.1@855,590.99 C18.2@820,590.99
NetC23_2: C23.2 R21.1 | length 35
  L1-Top Layer w15: R21.1@1299,753 C23.2@1299,788
NetC24_1: C24.1 C26.1 L5.2 R24.2 U10.1 U10.2 | length 616.5
  L1-Top Layer w10: v1(921,809) 927,815 C24.1@946.01,815 948.02,815 R24.2@948.02,782.01 ; U10.2@1129.13,675.4 U10.1@1148.81,675.4 1148.81,685.81 1158.31,695.31 C26.1@1203,695.31 1203,728 1220.5,745.5 L5.2@1220.5,766 1220.5,814.5 v1(1220,815)
  L6-Bottom Layer w10: v1(921,809) 965.87,764.13 1169.13,764.13 v1(1220,815)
